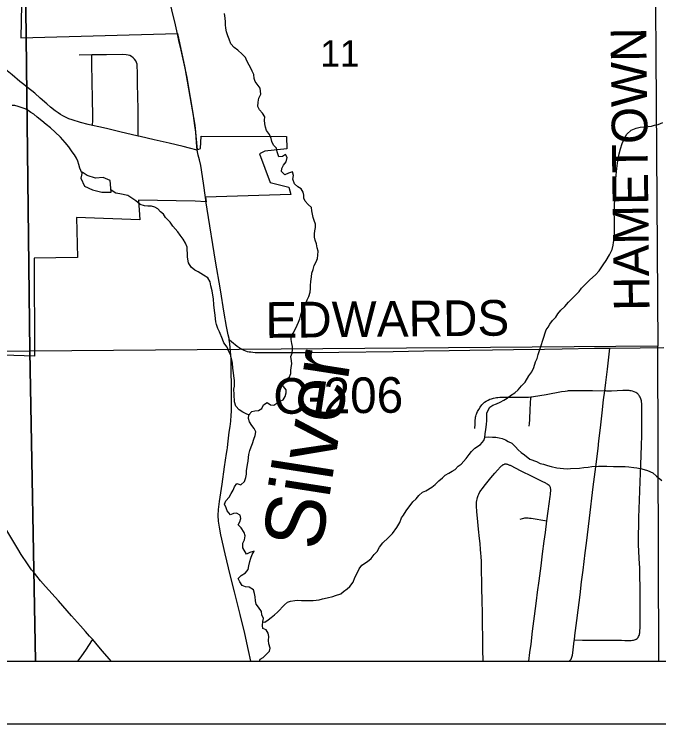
# Model space of a CAD drawing. Extents: x 0 to 34, y -5 to 22.
# Drawn here: x 4.121 to 5.148, y 14 to 15.13 of the extents above; entities that cross this region are included whole.
import ezdxf

# ---------------------------------------------------------------- set-up
doc = ezdxf.new("R2010")
doc.units = 0
for name, color, linetype in [('GM_X_City_Street', 7, 'Continuous'), ('GM_X_Corporation', 7, 'Continuous'), ('GM_X_County_Road', 7, 'Continuous'), ('GM_X_County_Road_Text', 7, 'Continuous'), ('GM_X_Minor_Lake', 7, 'Continuous'), ('GM_X_Minor_River', 7, 'Continuous'), ('GM_X_Minor_River_Text', 7, 'Continuous'), ('GM_X_Section', 7, 'Continuous'), ('GM_X_Section_Text', 7, 'Continuous'), ('GM_X_Township_Road', 7, 'Continuous'), ('GM_X_US_Route', 7, 'Continuous'), ('SH_Cut_Line', 7, 'Continuous'), ('SH_Data', 7, 'Continuous')]:
    doc.layers.add(name, color=color, linetype=linetype)

msp = doc.modelspace()

# ---------------------------------------------------------------- linework, layer by layer
at = {"layer": 'GM_X_City_Street'}
for points in [[(4.3186, 14.9363), (4.3186, 14.9383), (4.3185, 14.9606), (4.3183, 14.9792), (4.3177, 15.0195), (4.3174, 15.0381), (4.3172, 15.0474), (4.3169, 15.0505), (4.316, 15.0535), (4.3146, 15.0563), (4.3128, 15.0588), (4.3105, 15.061), (4.308, 15.0628), (4.3053, 15.0643), (4.3024, 15.0653), (4.2993, 15.0658), (4.2931, 15.066), (4.2682, 15.0657), (4.2496, 15.0656), (4.2449, 15.0656), (4.2246, 15.0653)], [(4.2459, 14.953), (4.2461, 14.9613), (4.2457, 15.0022), (4.2455, 15.0164), (4.245, 15.0575), (4.2449, 15.0638), (4.2449, 15.0656)]]:
    msp.add_lwpolyline(points, dxfattribs=at)
for points in [[(3.1115, 14.1), (4.1551, 14.1), (4.1458, 14.5934), (3.5359, 14.5917), (3.104, 14.6056)], [(4.1551, 14.1), (5.148, 14.1), (5.1465, 14.6013), (4.1458, 14.5934)]]:
    msp.add_lwpolyline(points, close=True, dxfattribs=at)
at = {"layer": 'GM_X_Corporation'}
msp.add_lwpolyline([(4.1417, 15.5953), (4.1319, 15.0927), (4.381, 15.0995), (4.393, 15.0451), (4.4087, 14.9534), (4.4124, 14.9141), (4.4177, 14.9162), (4.4187, 14.936), (4.5547, 14.9356), (4.5556, 14.9159), (4.5206, 14.9124), (4.5118, 14.9078), (4.5287, 14.8621), (4.5585, 14.8546), (4.5618, 14.843), (4.4256, 14.8387), (4.4267, 14.8312), (4.4095, 14.8327), (4.3192, 14.834), (4.3211, 14.8027), (4.2204, 14.8064), (4.2217, 14.7429), (4.153, 14.7416), (4.1535, 14.5858), (3.9379, 14.5927)], dxfattribs=at)
at = {"layer": 'GM_X_County_Road'}
for points in [[(4.1364, 15.0184), (4.1303, 15.0233), (4.1177, 15.0335), (4.107, 15.0421), (4.0999, 15.0484), (4.0968, 15.0514), (4.0921, 15.0564), (4.0878, 15.0613), (4.0841, 15.0653), (4.0807, 15.0687), (4.0785, 15.0709), (4.0776, 15.0718)], [(4.2459, 14.953), (4.239, 14.9546), (4.2266, 14.9578), (4.2136, 14.9618), (4.2083, 14.9638), (4.2041, 14.9656), (4.1987, 14.9684), (4.1947, 14.9706), (4.1912, 14.973), (4.1862, 14.9765), (4.179, 14.9823), (4.1729, 14.9876), (4.1627, 14.9964), (4.1537, 15.0043), (4.1425, 15.0136), (4.1364, 15.0184)], [(4.3186, 14.9363), (4.2895, 14.9432), (4.2683, 14.9481), (4.2561, 14.9508), (4.2459, 14.953)], [(4.4126, 14.9136), (4.4003, 14.9169), (4.3902, 14.9194), (4.3682, 14.9247), (4.3439, 14.9303), (4.3216, 14.9357), (4.3186, 14.9363)], [(4.4258, 14.8382), (4.4225, 14.8612), (4.4182, 14.8892), (4.4161, 14.8985), (4.4142, 14.9058), (4.4126, 14.9136)], [(4.427, 14.8297), (4.4269, 14.8307), (4.4258, 14.8382)], [(4.4636, 14.612), (4.4633, 14.614), (4.462, 14.6198), (4.4593, 14.6328), (4.4555, 14.6543), (4.4495, 14.6911), (4.4418, 14.7371), (4.4286, 14.82), (4.427, 14.8297)], [(4.4979, 14.1), (4.4946, 14.1167), (4.4885, 14.144), (4.4811, 14.1742), (4.4718, 14.2103), (4.465, 14.2375), (4.4571, 14.2708), (4.4501, 14.3011), (4.4479, 14.3134), (4.4468, 14.3227), (4.4462, 14.3318), (4.4468, 14.3415), (4.4482, 14.3539), (4.4522, 14.3816), (4.4563, 14.4092), (4.4594, 14.4305), (4.4602, 14.4365), (4.4608, 14.4396), (4.4615, 14.4456), (4.4625, 14.455), (4.4638, 14.4643), (4.4649, 14.4734), (4.466, 14.4821), (4.4667, 14.4915), (4.4671, 14.4976), (4.4673, 14.5038), (4.4674, 14.5162), (4.4673, 14.5348), (4.4668, 14.5657), (4.4668, 14.5689), (4.4665, 14.5811), (4.4661, 14.5871), (4.4656, 14.5932), (4.4645, 14.6055), (4.4636, 14.612)], [(4.4636, 14.612), (4.467, 14.6092), (4.4765, 14.6015), (4.4813, 14.5981), (4.4836, 14.5968), (4.4869, 14.5951), (4.4895, 14.5941), (4.4923, 14.5933), (4.4952, 14.5927), (4.4981, 14.5923), (4.501, 14.592), (4.5049, 14.5917), (4.5142, 14.5916), (4.5268, 14.5916), (4.5485, 14.5917), (4.5671, 14.5917), (4.595, 14.5917), (4.6384, 14.5922), (4.7249, 14.5933), (4.7736, 14.5942), (4.8138, 14.5949), (4.8468, 14.5953), (4.8828, 14.5957), (4.9164, 14.596), (4.966, 14.5969), (4.994, 14.5974), (5.0458, 14.5982), (5.0702, 14.5986)], [(5.0702, 14.5986), (5.1182, 14.5991), (5.1559, 14.5996)]]:
    msp.add_lwpolyline(points, dxfattribs=at)
at = {"layer": 'GM_X_Minor_Lake'}
for points in [[(4.274, 14.8656), (4.2629, 14.87), (4.2504, 14.8692), (4.2375, 14.8732), (4.2291, 14.8785), (4.2273, 14.8694), (4.2331, 14.8565), (4.2456, 14.8505), (4.2608, 14.8468), (4.2756, 14.847)], [(4.2756, 14.847), (4.274, 14.8656)]]:
    msp.add_lwpolyline(points, dxfattribs=at)
at = {"layer": 'GM_X_Minor_River'}
for points in [[(4.6006, 14.7702), (4.5997, 14.7751), (4.5996, 14.7804), (4.5999, 14.7854), (4.6009, 14.7907), (4.6012, 14.7961), (4.5992, 14.8017), (4.5976, 14.8067), (4.5963, 14.8116), (4.5951, 14.8173), (4.5946, 14.8222), (4.5896, 14.8274), (4.5845, 14.8323), (4.5825, 14.8372), (4.5824, 14.8421), (4.5816, 14.8471), (4.578, 14.8523), (4.5727, 14.8553), (4.5676, 14.8601), (4.5652, 14.8673), (4.5658, 14.8734), (4.5646, 14.8791), (4.5581, 14.8771), (4.5521, 14.8743), (4.5471, 14.8795), (4.5473, 14.8845), (4.5499, 14.8898), (4.5544, 14.8953), (4.5558, 14.9018), (4.5534, 14.9067), (4.5485, 14.9039), (4.5428, 14.903), (4.54, 14.911), (4.5387, 14.917), (4.5341, 14.9219), (4.5317, 14.9276), (4.5304, 14.9325), (4.528, 14.9385), (4.523, 14.9449), (4.5213, 14.9506), (4.5201, 14.9555), (4.52, 14.9616), (4.5202, 14.9669), (4.5167, 14.9729), (4.5117, 14.9782), (4.5093, 14.9834), (4.5095, 14.9903), (4.5109, 14.9964), (4.5138, 15.0029), (4.5129, 15.0124), (4.5051, 15.0229), (4.5035, 15.0279), (4.5026, 15.0343), (4.5002, 15.0396), (4.4978, 15.0445), (4.4954, 15.0494), (4.4919, 15.0558), (4.4895, 15.0611), (4.4841, 15.0667), (4.4771, 15.073), (4.4713, 15.0771), (4.4662, 15.0831), (4.4634, 15.0906), (4.4614, 15.0956), (4.4594, 15.102), (4.4581, 15.108), (4.4576, 15.1134), (4.4576, 15.1183), (4.4571, 15.124), (4.4562, 15.1316)], [(4.229, 14.8779), (4.2257, 14.8851), (4.2241, 14.8908), (4.2224, 14.8961), (4.2201, 14.901), (4.2169, 14.9063), (4.2134, 14.9112), (4.2079, 14.9191), (4.2024, 14.9258), (4.195, 14.9344), (4.1861, 14.9426), (4.1788, 14.9493), (4.1718, 14.9545), (4.1652, 14.9605), (4.1579, 14.9664), (4.1525, 14.9713), (4.1478, 14.9738), (4.1432, 14.9768), (4.1386, 14.9794), (4.1321, 14.9819), (4.1275, 14.9833), (4.1221, 14.9848), (4.1176, 14.9851)], [(5.0249, 14.6938), (5.0309, 14.6997), (5.038, 14.7074), (5.0474, 14.7152), (5.0529, 14.7218), (5.0592, 14.731), (5.0644, 14.738), (5.0696, 14.7468), (5.0736, 14.7556), (5.0754, 14.7622), (5.0757, 14.7667), (5.0767, 14.7713), (5.0776, 14.7839), (5.0772, 14.8044), (5.077, 14.8136), (5.0776, 14.8246), (5.0781, 14.8368), (5.0779, 14.8501), (5.0788, 14.8623), (5.0801, 14.8741), (5.081, 14.8844), (5.082, 14.8928), (5.0834, 14.9004), (5.0847, 14.9077), (5.0869, 14.9157), (5.0897, 14.9245), (5.0927, 14.9311), (5.0971, 14.9391), (5.1038, 14.9454), (5.1117, 14.9489), (5.1182, 14.9506), (5.1254, 14.9511), (5.1311, 14.9516), (5.1364, 14.9521), (5.141, 14.9537), (5.147, 14.9546), (5.1546, 14.9578)], [(4.4957, 14.4928), (4.4956, 14.4915), (4.4898, 14.4941), (4.4852, 14.4966), (4.4794, 14.5003), (4.4744, 14.5059), (4.4719, 14.5131), (4.4713, 14.5245), (4.4712, 14.5329), (4.4718, 14.5379), (4.472, 14.5466), (4.4711, 14.5542), (4.4707, 14.5588), (4.4694, 14.5663), (4.4688, 14.5743), (4.4676, 14.58), (4.4659, 14.5884), (4.4631, 14.5932), (4.4604, 14.5997), (4.4553, 14.6068), (4.4529, 14.6125), (4.4481, 14.6242), (4.4453, 14.6298), (4.4433, 14.6359), (4.4424, 14.6404), (4.442, 14.645), (4.4411, 14.6511), (4.4402, 14.6583), (4.4393, 14.6674), (4.4387, 14.6769), (4.4374, 14.6826), (4.4362, 14.6898), (4.4345, 14.6977), (4.4332, 14.7042), (4.4293, 14.7106), (4.4227, 14.7146), (4.4139, 14.7202), (4.4089, 14.7227), (4.4031, 14.7272), (4.3988, 14.7343), (4.3974, 14.7434), (4.3969, 14.7495), (4.3968, 14.7545), (4.3964, 14.7594), (4.394, 14.7655), (4.39, 14.7718), (4.3857, 14.7782), (4.3818, 14.7835), (4.3736, 14.7925), (4.3697, 14.7992), (4.3623, 14.8063), (4.3588, 14.812), (4.3542, 14.8157), (4.3499, 14.8202), (4.3453, 14.8227), (4.3399, 14.8245), (4.3338, 14.8248), (4.3285, 14.8251), (4.322, 14.8272), (4.3146, 14.8332), (4.3019, 14.8413), (4.2893, 14.8441), (4.2832, 14.8451), (4.2753, 14.8502)], [(4.5032, 14.2751), (4.4964, 14.2731), (4.4911, 14.2703), (4.4852, 14.2801), (4.4854, 14.2877), (4.488, 14.2931), (4.489, 14.2996), (4.4874, 14.3049), (4.4827, 14.312), (4.478, 14.3169), (4.4806, 14.3219), (4.482, 14.3272), (4.4808, 14.3325), (4.4754, 14.3355), (4.4704, 14.335), (4.4655, 14.333), (4.4601, 14.339), (4.4585, 14.3439), (4.4561, 14.3496), (4.4582, 14.3553), (4.4635, 14.3611), (4.4668, 14.3669), (4.4701, 14.3723), (4.4719, 14.3773), (4.476, 14.3827), (4.4821, 14.3809), (4.4877, 14.3859), (4.4899, 14.3924), (4.4909, 14.3978), (4.4912, 14.4031), (4.4925, 14.413), (4.4936, 14.4184), (4.4942, 14.4241), (4.4949, 14.4291), (4.4967, 14.4356), (4.4984, 14.4413), (4.5006, 14.4463), (4.5028, 14.4532), (4.505, 14.459), (4.506, 14.4651), (4.5032, 14.4703), (4.4997, 14.4752), (4.4958, 14.4808), (4.4941, 14.4865), (4.4948, 14.4919), (4.4996, 14.4973), (4.5046, 14.4985), (4.5103, 14.499), (4.5155, 14.5025), (4.5181, 14.5079), (4.5241, 14.5118), (4.5295, 14.5081), (4.5345, 14.5078), (4.5394, 14.5106), (4.5446, 14.5138), (4.5495, 14.5161), (4.5529, 14.5211), (4.5543, 14.5273), (4.5542, 14.5322), (4.5503, 14.5371), (4.5475, 14.542), (4.5546, 14.5486), (4.5599, 14.5529), (4.5617, 14.5578), (4.5619, 14.5628), (4.5622, 14.5677), (4.5636, 14.5735), (4.5628, 14.5784), (4.5619, 14.5849), (4.5641, 14.5906), (4.5647, 14.596), (4.5643, 14.6009), (4.5634, 14.6058), (4.5625, 14.6119), (4.5624, 14.6168), (4.5654, 14.6222), (4.569, 14.6291), (4.572, 14.6349), (4.5742, 14.6399), (4.576, 14.6449), (4.5777, 14.6514), (4.5792, 14.6564), (4.5813, 14.6625), (4.585, 14.669), (4.5876, 14.6752), (4.5905, 14.6809), (4.5926, 14.6878), (4.5929, 14.6932), (4.5932, 14.6981), (4.5938, 14.7046), (4.5945, 14.7122), (4.5955, 14.7179), (4.5973, 14.7237), (4.5987, 14.7298), (4.602, 14.736), (4.6042, 14.7413), (4.6048, 14.7467), (4.6051, 14.7528), (4.6038, 14.7584), (4.6026, 14.7645), (4.6006, 14.7702)], [(4.5171, 14.1624), (4.5202, 14.162), (4.5259, 14.1656), (4.5307, 14.1691), (4.536, 14.1734), (4.5408, 14.178), (4.5517, 14.1893), (4.5565, 14.1936), (4.5611, 14.1955), (4.5679, 14.1964), (4.5728, 14.1969), (4.5786, 14.1963), (4.5907, 14.1965), (4.5976, 14.1962), (4.6071, 14.1976), (4.6124, 14.1992), (4.6196, 14.2009), (4.6287, 14.2029), (4.6332, 14.2045), (4.6412, 14.207), (4.6457, 14.2105), (4.6513, 14.2148), (4.6558, 14.2187), (4.661, 14.2256), (4.6639, 14.2333), (4.6686, 14.2421), (4.6704, 14.2471), (4.6749, 14.2525), (4.6839, 14.2588), (4.6895, 14.2635), (4.6948, 14.2697), (4.6992, 14.2743), (4.7033, 14.2812), (4.7081, 14.2882), (4.7171, 14.2963), (4.7238, 14.3033), (4.7308, 14.3126), (4.7353, 14.3207), (4.7382, 14.3279), (4.7415, 14.3326), (4.7456, 14.3391), (4.7559, 14.3538), (4.7612, 14.3581), (4.7656, 14.3635), (4.7716, 14.3689), (4.7769, 14.3713), (4.7863, 14.3772), (4.7919, 14.3811), (4.7975, 14.3869), (4.8032, 14.392), (4.8076, 14.3959), (4.8137, 14.399), (4.8189, 14.4022), (4.8234, 14.4053), (4.8283, 14.4104), (4.8332, 14.4135), (4.841, 14.4224), (4.8458, 14.429), (4.8495, 14.4336), (4.8548, 14.439), (4.8638, 14.4449), (4.8694, 14.4511), (4.8708, 14.4561), (4.8715, 14.4618), (4.8725, 14.4687), (4.8735, 14.4767), (4.8741, 14.4832), (4.874, 14.4904), (4.8742, 14.4953), (4.879, 14.5046), (4.8835, 14.5077), (4.8896, 14.5097), (4.8952, 14.5121), (4.9013, 14.5153), (4.9065, 14.5188), (4.9118, 14.5231), (4.9189, 14.5274), (4.9241, 14.5321), (4.9294, 14.5383), (4.9349, 14.5444), (4.9412, 14.5541), (4.9457, 14.5606), (4.949, 14.5675), (4.9515, 14.5764), (4.954, 14.5821), (4.9558, 14.5882), (4.958, 14.5947), (4.9605, 14.6028), (4.9633, 14.6112), (4.9684, 14.6273), (4.9717, 14.6319), (4.9743, 14.6365), (4.9787, 14.6423), (4.984, 14.6478), (4.9873, 14.6528), (4.9921, 14.6589), (4.9981, 14.6648), (5.0041, 14.6714), (5.0141, 14.6818), (5.0212, 14.6888), (5.0249, 14.6938)], [(4.8709, 14.4565), (4.8773, 14.457), (4.883, 14.4567), (4.8883, 14.4564), (4.8937, 14.4554), (4.8982, 14.4543), (4.9036, 14.4521), (4.9082, 14.4499), (4.9136, 14.447), (4.9198, 14.441), (4.9237, 14.4365), (4.9287, 14.4321), (4.9338, 14.4284), (4.9423, 14.4217), (4.953, 14.4177), (4.9588, 14.4148), (4.9645, 14.4137), (4.9706, 14.4112), (4.9764, 14.4098), (4.9855, 14.408), (4.9962, 14.4067), (5.0019, 14.4064), (5.0073, 14.4069), (5.0217, 14.4072), (5.0286, 14.4085), (5.0354, 14.409), (5.0411, 14.4099), (5.0517, 14.4104), (5.0574, 14.4106), (5.0651, 14.4103), (5.0757, 14.4101), (5.0849, 14.4096), (5.0944, 14.4097), (5.1001, 14.4091), (5.1081, 14.4085), (5.1131, 14.4078), (5.1207, 14.4064), (5.1299, 14.4036), (5.1383, 14.3999), (5.1445, 14.3943), (5.1527, 14.3873)], [(4.5119, 14.1), (4.513, 14.1029), (4.5179, 14.1057), (4.5276, 14.1158), (4.529, 14.1207), (4.5266, 14.1275), (4.5261, 14.1328), (4.5268, 14.1393), (4.5259, 14.1446), (4.5224, 14.1495), (4.5174, 14.1517), (4.5165, 14.1566), (4.5172, 14.1627), (4.5182, 14.1677), (4.5158, 14.1734), (4.5149, 14.1791), (4.5102, 14.1858), (4.5067, 14.1907), (4.5055, 14.196), (4.505, 14.2025), (4.5037, 14.2074), (4.5021, 14.2134), (4.4952, 14.2179), (4.4894, 14.2182), (4.4841, 14.2203), (4.4805, 14.226), (4.4778, 14.2316), (4.4826, 14.2363), (4.4898, 14.2406), (4.4939, 14.2456), (4.4949, 14.2514), (4.4963, 14.2586), (4.4981, 14.264), (4.5002, 14.2697), (4.5032, 14.2751)]]:
    msp.add_lwpolyline(points, dxfattribs=at)
at = {"layer": 'GM_X_Section'}
for points in [[(3.1044, 15.6177), (3.6228, 15.592), (4.1342, 15.5936), (4.1458, 14.5934), (3.5359, 14.5917), (3.104, 14.6056)], [(4.1342, 15.5936), (5.1393, 15.6065), (5.1465, 14.6013), (4.1458, 14.5934)]]:
    msp.add_lwpolyline(points, close=True, dxfattribs=at)
at = {"layer": 'GM_X_Township_Road'}
for points in [[(4.3812, 15.0989), (4.3778, 15.1133), (4.372, 15.1374), (4.3666, 15.1616), (4.3634, 15.1768), (4.3596, 15.1979), (4.3561, 15.2177), (4.3529, 15.2354), (4.3503, 15.25), (4.3486, 15.2591), (4.3461, 15.2734), (4.3419, 15.2963), (4.3402, 15.3071), (4.3349, 15.3375), (4.3308, 15.3589), (4.327, 15.3797), (4.324, 15.3971)], [(4.4126, 14.9136), (4.4117, 14.9259), (4.411, 14.9342), (4.4102, 14.9426), (4.4089, 14.9529), (4.4066, 14.969), (4.4039, 14.9853), (4.4019, 14.9977), (4.3992, 15.0138), (4.3964, 15.0294), (4.3932, 15.0446), (4.3873, 15.0729), (4.3836, 15.0884), (4.3812, 15.0989)], [(5.0619, 14.5306), (5.0635, 14.5434), (5.0664, 14.5649), (5.0702, 14.5986)], [(4.9439, 14.5206), (4.9457, 14.5208), (4.9482, 14.5212), (4.9683, 14.5247), (4.9928, 14.5292), (4.999, 14.5301), (5.0023, 14.5305), (5.0042, 14.5307), (5.0078, 14.5309), (5.0113, 14.531), (5.0146, 14.531), (5.0233, 14.531), (5.0423, 14.5309), (5.0619, 14.5306)], [(5.0135, 14.1338), (5.0266, 14.1333), (5.0388, 14.133), (5.0521, 14.133), (5.0634, 14.133), (5.0734, 14.1331), (5.0789, 14.1331), (5.0844, 14.133), (5.0887, 14.133), (5.0939, 14.1328), (5.0981, 14.1327), (5.1015, 14.1328), (5.1038, 14.1328), (5.106, 14.133), (5.1078, 14.1333), (5.1095, 14.1338), (5.111, 14.1344), (5.1122, 14.135), (5.1133, 14.1358), (5.1141, 14.1365), (5.115, 14.1376), (5.1159, 14.1391), (5.1166, 14.1405), (5.1171, 14.1422), (5.1174, 14.1433), (5.1177, 14.1451), (5.1179, 14.147), (5.118, 14.1492), (5.1181, 14.1517), (5.1182, 14.1568), (5.1182, 14.1644), (5.1182, 14.1773), (5.1182, 14.1982), (5.1181, 14.2107), (5.1181, 14.2204), (5.118, 14.2324), (5.1178, 14.2395), (5.1176, 14.2479), (5.1168, 14.2634), (5.1162, 14.2755), (5.1158, 14.2843), (5.1157, 14.2872), (5.1157, 14.2912), (5.1157, 14.2958), (5.1157, 14.2989), (5.1162, 14.3184), (5.1164, 14.3286), (5.1172, 14.3563), (5.1183, 14.3862), (5.1188, 14.3989), (5.1192, 14.412), (5.1198, 14.4282), (5.1202, 14.4427), (5.1207, 14.4596), (5.121, 14.4797), (5.1211, 14.4925), (5.1212, 14.4998), (5.1212, 14.5046), (5.121, 14.5081), (5.1209, 14.5104), (5.1206, 14.5127), (5.1203, 14.5144), (5.12, 14.5159), (5.1196, 14.5175), (5.1189, 14.5191), (5.1183, 14.5205), (5.1175, 14.5218), (5.1166, 14.5232), (5.1153, 14.5245), (5.1144, 14.5255), (5.113, 14.5266), (5.1116, 14.5275), (5.1087, 14.5289), (5.1063, 14.5297), (5.1041, 14.5303), (5.1024, 14.5306), (5.1007, 14.5308), (5.0987, 14.5309), (5.0956, 14.5309), (5.0906, 14.5307), (5.0724, 14.5298), (5.0694, 14.5298), (5.0672, 14.5298), (5.0653, 14.53), (5.0634, 14.5304), (5.0619, 14.5306)], [(5.0135, 14.1338), (5.0143, 14.1407), (5.0173, 14.1644), (5.0194, 14.1811), (5.0225, 14.2054), (5.0251, 14.2264), (5.0273, 14.2447), (5.0306, 14.2725), (5.0327, 14.2877), (5.0376, 14.3277), (5.0434, 14.3773), (5.0475, 14.4094), (5.0512, 14.4387), (5.0526, 14.4505), (5.055, 14.4717), (5.0577, 14.4951), (5.0601, 14.5158), (5.0619, 14.5306)], [(4.855, 14.4704), (4.8552, 14.4774), (4.8552, 14.4793), (4.8553, 14.4816), (4.8554, 14.4839), (4.8558, 14.4863), (4.8562, 14.4887), (4.8566, 14.4903), (4.8571, 14.4919), (4.8576, 14.4933), (4.8581, 14.495), (4.8593, 14.4976), (4.8611, 14.5008), (4.8635, 14.5046), (4.866, 14.5079), (4.868, 14.5101), (4.8705, 14.5123), (4.873, 14.514), (4.8759, 14.5156), (4.8788, 14.5169), (4.8817, 14.5179), (4.8847, 14.5188), (4.8873, 14.5193), (4.8894, 14.5196), (4.8916, 14.5199), (4.8949, 14.5201), (4.9006, 14.5203), (4.9128, 14.5204), (4.924, 14.5204), (4.936, 14.5204), (4.9404, 14.5205), (4.9439, 14.5206)], [(4.9416, 14.4739), (4.9419, 14.4786), (4.9423, 14.484), (4.9431, 14.5015), (4.9435, 14.5094), (4.9439, 14.5206)], [(4.8682, 14.1), (4.8681, 14.1045), (4.8679, 14.1136), (4.8678, 14.1256), (4.8675, 14.1428), (4.8673, 14.1534), (4.867, 14.1721), (4.8665, 14.2006), (4.8663, 14.2117), (4.8661, 14.2259), (4.8657, 14.243), (4.8655, 14.2529), (4.8653, 14.2587), (4.8649, 14.2667), (4.8645, 14.2719), (4.8641, 14.2778), (4.8632, 14.2873), (4.8625, 14.295), (4.861, 14.31), (4.8594, 14.3276), (4.8583, 14.3379), (4.858, 14.341), (4.8578, 14.3441), (4.8577, 14.3469), (4.8577, 14.3506), (4.8577, 14.3517), (4.8578, 14.353), (4.8582, 14.3556), (4.8586, 14.358), (4.8593, 14.3607), (4.8603, 14.3638), (4.8612, 14.3659), (4.8629, 14.3693), (4.8648, 14.3721), (4.8665, 14.3745), (4.8717, 14.3812), (4.8805, 14.3917), (4.8867, 14.399), (4.891, 14.4038), (4.8957, 14.4091), (4.8965, 14.4099), (4.8974, 14.4108), (4.8985, 14.4117), (4.8997, 14.4125), (4.9002, 14.4128), (4.9009, 14.4131), (4.902, 14.4134)], [(4.9705, 14.3817), (4.9692, 14.3825), (4.968, 14.3831), (4.9668, 14.3837), (4.9631, 14.3856), (4.946, 14.394), (4.9288, 14.4025), (4.9115, 14.4112), (4.9107, 14.4115), (4.9096, 14.412), (4.9085, 14.4124), (4.9073, 14.4128), (4.9063, 14.4131), (4.9056, 14.4134), (4.9048, 14.4135), (4.9039, 14.4136), (4.9032, 14.4136), (4.902, 14.4134)], [(4.9695, 14.3233), (4.9715, 14.3386), (4.9749, 14.3619), (4.9754, 14.3651), (4.9757, 14.3681), (4.9759, 14.3705), (4.9759, 14.3725), (4.9759, 14.3737), (4.9757, 14.3749), (4.9753, 14.3763), (4.9747, 14.3775), (4.9742, 14.3783), (4.9737, 14.379), (4.9731, 14.3797), (4.972, 14.3806), (4.9705, 14.3817)], [(4.9273, 14.3258), (4.9307, 14.3269), (4.9329, 14.3275), (4.9345, 14.3279), (4.9361, 14.3281), (4.9382, 14.3281), (4.94, 14.328), (4.9422, 14.3278), (4.9448, 14.3274), (4.9695, 14.3233)], [(4.9411, 14.1), (4.9428, 14.1138), (4.9444, 14.1269), (4.9469, 14.1477), (4.9499, 14.1714), (4.953, 14.1957), (4.9549, 14.2099), (4.9573, 14.2277), (4.9604, 14.2519), (4.9629, 14.2707), (4.9655, 14.2908), (4.9673, 14.3049), (4.9695, 14.3233)], [(4.2461, 14.1341), (4.2412, 14.1398), (4.2348, 14.1471), (4.2269, 14.156), (4.2124, 14.1722), (4.1915, 14.1959), (4.1711, 14.2189), (4.1632, 14.228), (4.1569, 14.2353), (4.1532, 14.2399), (4.1486, 14.2455), (4.1455, 14.2498), (4.142, 14.2548), (4.1322, 14.2699), (4.127, 14.2785), (4.1032, 14.3185)], [(4.2222, 14.1), (4.2275, 14.1067), (4.236, 14.1188), (4.2447, 14.132), (4.2461, 14.1341)], [(4.2754, 14.1), (4.2729, 14.1031), (4.2614, 14.1165), (4.2511, 14.1283), (4.2461, 14.1341)], [(5.0052, 14.1), (5.0061, 14.1007), (5.0073, 14.1019), (5.0083, 14.1031), (5.0091, 14.1045), (5.0096, 14.1059), (5.0101, 14.1077), (5.0104, 14.1095), (5.011, 14.1129), (5.0133, 14.1324), (5.0135, 14.1338)]]:
    msp.add_lwpolyline(points, dxfattribs=at)
at = {"layer": 'GM_X_US_Route'}
msp.add_lwpolyline([(2.1, 16.5221), (2.1, 14.1), (6.156, 14.1)], dxfattribs=at)
at = {"layer": 'SH_Cut_Line'}
msp.add_lwpolyline([(2.1, 16.5221), (2.1, 14.1), (6.156, 14.1)], dxfattribs=at)
at = {"layer": 'SH_Data'}
for p, q in [((2.1, 14.1), (8.9, 14.1)), ((2, 14), (9, 14))]:
    msp.add_line(p, q, dxfattribs=at)

# ---------------------------------------------------------------- texts
at = {"layer": 'GM_X_County_Road_Text'}
for s, rotation, p in [('HAMETOWN', 90.6915, (5.1333, 14.658)), ('EDWARDS', 0.5537, (4.5216, 14.6147)), ('C-206', 0.5526, (4.5341, 14.4936))]:
    msp.add_text(s, height=0.05682, rotation=rotation, dxfattribs=at).set_placement(p)
at = {"layer": 'GM_X_Minor_River_Text'}
msp.add_text('Silver', height=0.09474, rotation=81.0963, dxfattribs=at).set_placement((4.6097, 14.2739))
at = {"layer": 'GM_X_Section_Text'}
msp.add_text('11', height=0.04186, rotation=0, dxfattribs=at).set_placement((4.6089, 15.047))

doc.saveas('drawing.dxf')
